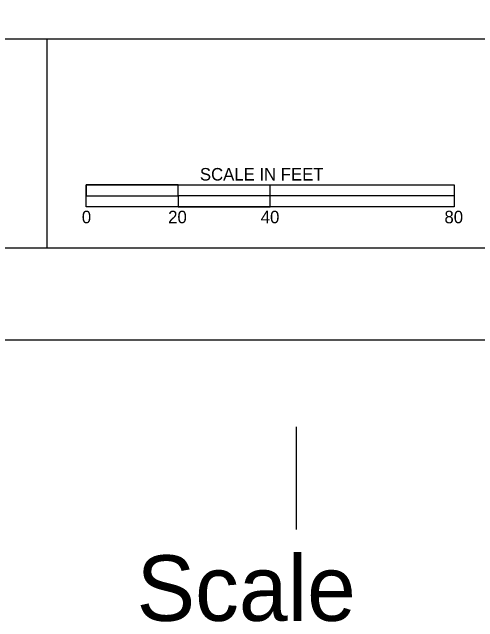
# Model space of a CAD drawing. Extents: x 2157704 to 2158404, y 1040586 to 1041166.
# Drawn here: x 2158101.6 to 2158202.9, y 1040590.9 to 1040723.5 of the extents above; entities that cross this region are included whole.
import ezdxf

# ---------------------------------------------------------------- set-up
doc = ezdxf.new("R2010")
doc.units = 0
for name, color, linetype in [('SHT_B_Grid-Major-Line', 7, 'Continuous'), ('SHT_B_North-Arrow', 7, 'Continuous'), ('UTLE_E_UG-Wat-Line-30-Qual-B-50', 7, 'Continuous'), ('UTLE_E_UG-Wat-Line-30-Qual-C-50', 7, 'Continuous')]:
    doc.layers.add(name, color=color, linetype=linetype)

msp = doc.modelspace()

# ---------------------------------------------------------------- linework, layer by layer
at = {"layer": 'SHT_B_Grid-Major-Line'}
for points in [[(2158117.75, 1040685.93), (2158197.75, 1040685.93), (2158197.75, 1040681.13), (2158117.75, 1040681.13)], [(2158117.75, 1040683.53), (2158137.75, 1040683.53), (2158137.75, 1040685.93), (2158117.75, 1040685.93)], [(2158197.75, 1040683.53), (2158157.75, 1040683.53), (2158157.75, 1040685.93), (2158197.75, 1040685.93)], [(2158157.75, 1040683.53), (2158137.75, 1040683.53), (2158137.75, 1040681.13), (2158157.75, 1040681.13)]]:
    msp.add_lwpolyline(points, close=True, dxfattribs=at)
at = {"layer": 'SHT_B_North-Arrow'}
for p, q in [((2157773.99, 1040717.65), (2158393.99, 1040717.65)), ((2158109.25, 1040672.15), (2158109.25, 1040717.65)), ((2158157.75, 1040683.53), (2158157.75, 1040683.53)), ((2158163.49, 1040610.97), (2158163.49, 1040633.27))]:
    msp.add_line(p, q, dxfattribs=at)
at = {"layer": 'UTLE_E_UG-Wat-Line-30-Qual-B-50'}
msp.add_lwpolyline([(2157733.99, 1041092.15), (2158393.99, 1041092.15), (2158393.99, 1040672.15), (2157733.99, 1040672.15)], close=True, dxfattribs=at)
at = {"layer": 'UTLE_E_UG-Wat-Line-30-Qual-C-50'}
msp.add_lwpolyline([(2157703.99, 1041112.15), (2158403.99, 1041112.15), (2158403.99, 1040652.15), (2157703.99, 1040652.15)], close=True, dxfattribs=at)

# ---------------------------------------------------------------- texts
at = {"layer": 'SHT_B_Grid-Major-Line'}
for s, p in [('SCALE IN FEET', (2158142.47, 1040686.85)), ('0', (2158116.79, 1040677.55)), ('20', (2158135.57, 1040677.55)), ('40', (2158155.7, 1040677.55)), ('80', (2158195.65, 1040677.55))]:
    msp.add_text(s, height=2.72, rotation=360, dxfattribs=at).set_placement(p)
at = {"layer": 'SHT_B_North-Arrow'}
msp.add_text('Scale', height=14.25, rotation=0, dxfattribs=at).set_placement((2158128.71, 1040591.07))

doc.saveas('drawing.dxf')
